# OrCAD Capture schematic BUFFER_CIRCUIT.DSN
size A
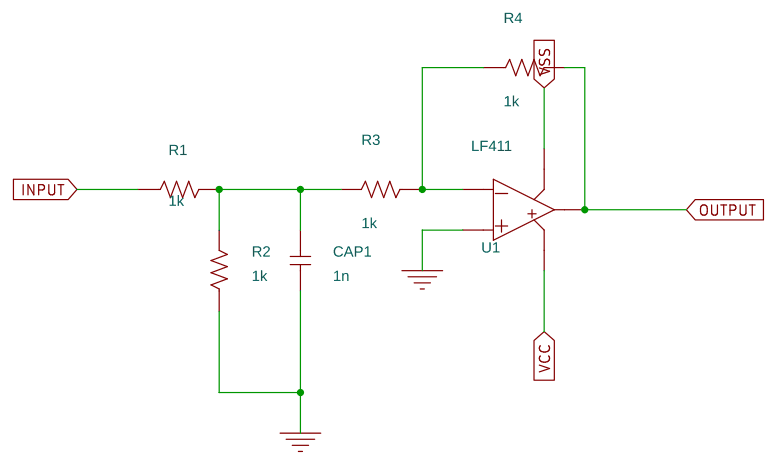
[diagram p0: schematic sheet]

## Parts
CAP1  1n  [CK05]
R1  1k  [RC05]
R2  1k  [RC05]
R3  1k  [RC05]
R4  1k  [RC05]
U1  LF411  [DIP1008W300L450]

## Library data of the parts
CAP1 = C
R1-R4 = R
U1 = LF411

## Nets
VCC: U1.7(PVSS)
VSS: U1.4(NVSS)
0: CAP1.1 R2.1 U1.3(PIN)
INPUT: R1.1
OUTPUT: R4.2 U1.6(OUT)
N00363: CAP1.2 R1.2 R2.2 R3.2
N00384: R3.1 R4.1 U1.2(NIN)
